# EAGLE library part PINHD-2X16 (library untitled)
PIN HEADER
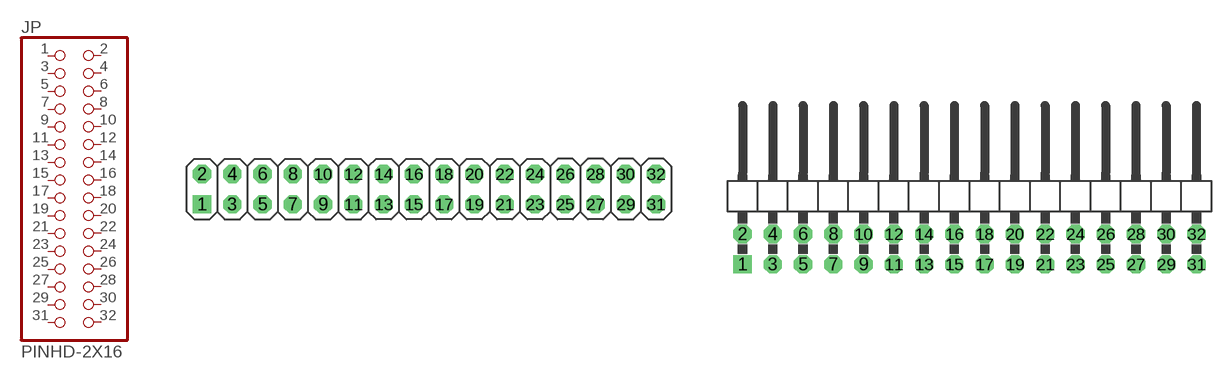
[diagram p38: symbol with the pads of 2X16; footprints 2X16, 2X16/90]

Designator prefix JP

## PINHD-2X16_2.54  [2X16]
1  1  pas
2  2  pas
3  3  pas
4  4  pas
5  5  pas
6  6  pas
7  7  pas
8  8  pas
9  9  pas
10  10  pas
11  11  pas
12  12  pas
13  13  pas
14  14  pas
15  15  pas
16  16  pas
17  17  pas
18  18  pas
19  19  pas
20  20  pas
21  21  pas
22  22  pas
23  23  pas
24  24  pas
25  25  pas
26  26  pas
27  27  pas
28  28  pas
29  29  pas
30  30  pas
31  31  pas
32  32  pas

## PINHD-2X16_2.54-90°  [2X16/90]
Pads as for 2X16

## PINHD-2X16_2.00  [2X16M]
Pads as for 2X16

## PINHD-2X16_2.54-SMD  [2X16SMD]
Pads as for 2X16

## PINHD-2X16_2.54-SMD-90°  [2X16SMD/90]
Pads as for 2X16

## Footprint 2X16 (pad centres in mm)
PIN HEADER - 2.54
drill 1.016 square: 1 -19.05,-1.27
drill 1.016 octagon: 2 -19.05,1.27; 3 -16.51,-1.27; 4 -16.51,1.27; 5 -13.97,-1.27; 6 -13.97,1.27; 7 -11.43,-1.27; 8 -11.43,1.27; 9 -8.89,-1.27; 10 -8.89,1.27; 11 -6.35,-1.27; 12 -6.35,1.27; 13 -3.81,-1.27; 14 -3.81,1.27; 15 -1.27,-1.27; 16 -1.27,1.27; 17 1.27,-1.27; 18 1.27,1.27; 19 3.81,-1.27; 20 3.81,1.27; 21 6.35,-1.27; 22 6.35,1.27; 23 8.89,-1.27; 24 8.89,1.27; 25 11.43,-1.27; 26 11.43,1.27; 27 13.97,-1.27; 28 13.97,1.27; 29 16.51,-1.27; 30 16.51,1.27; 31 19.05,-1.27; 32 19.05,1.27

## Footprint 2X16/90 (pad centres in mm)
PIN HEADER - 2.54 90°
drill 1.016 square: 1 -19.05,-6.35
drill 1.016 octagon: 2 -19.05,-3.81; 3 -16.51,-6.35; 4 -16.51,-3.81; 5 -13.97,-6.35; 6 -13.97,-3.81; 7 -11.43,-6.35; 8 -11.43,-3.81; 9 -8.89,-6.35; 10 -8.89,-3.81; 11 -6.35,-6.35; 12 -6.35,-3.81; 13 -3.81,-6.35; 14 -3.81,-3.81; 15 -1.27,-6.35; 16 -1.27,-3.81; 17 1.27,-6.35; 18 1.27,-3.81; 19 3.81,-6.35; 20 3.81,-3.81; 21 6.35,-6.35; 22 6.35,-3.81; 23 8.89,-6.35; 24 8.89,-3.81; 25 11.43,-6.35; 26 11.43,-3.81; 27 13.97,-6.35; 28 13.97,-3.81; 29 16.51,-6.35; 30 16.51,-3.81; 31 19.05,-6.35; 32 19.05,-3.81

## Footprint 2X16M (pad centres in mm)
PIN HEADER - 2
drill 0.914 square: 1 -15,-1
drill 0.914 round: 2 -15,1; 3 -13,-1; 4 -13,1; 5 -11,-1; 6 -11,1; 7 -9,-1; 8 -9,1; 9 -7,-1; 10 -7,1; 11 -5,-1; 12 -5,1; 13 -3,-1; 14 -3,1; 15 -1,-1; 16 -1,1; 17 1,-1; 18 1,1; 19 3,-1; 20 3,1; 21 5,-1; 22 5,1; 23 7,-1; 24 7,1; 25 9,-1; 26 9,1; 27 11,-1; 28 11,1; 29 13,-1; 30 13,1; 31 15,-1; 32 15,1

## Footprint 2X16SMD (pad centres in mm)
PIN HEADER - 2.54 SMD
smd 1.016 x 3.302: 1 -1.27,-3.81; 2 -1.27,1.27; 3 1.27,-3.81; 4 1.27,1.27; 5 3.81,-3.81; 6 3.81,1.27; 7 6.35,-3.81; 8 6.35,1.27; 9 8.89,-3.81; 10 8.89,1.27; 11 11.43,-3.81; 12 11.43,1.27; 13 13.97,-3.81; 14 13.97,1.27; 15 16.51,-3.81; 16 16.51,1.27; 17 19.05,-3.81; 18 19.05,1.27; 19 21.59,-3.81; 20 21.59,1.27; 21 24.13,-3.81; 22 24.13,1.27; 23 26.67,-3.81; 24 26.67,1.27; 25 29.21,-3.81; 26 29.21,1.27; 27 31.75,-3.81; 28 31.75,1.27; 29 34.29,-3.81; 30 34.29,1.27; 31 36.83,-3.81; 32 36.83,1.27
